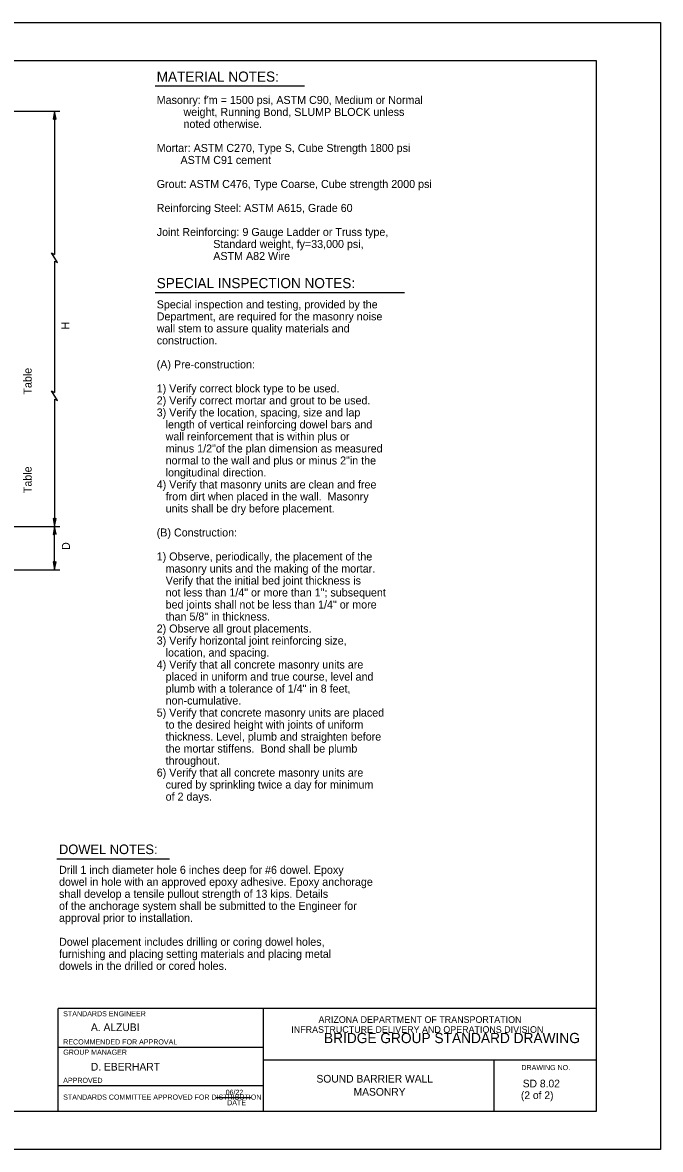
# Model space of a CAD drawing. Extents: x 0 to 2.83, y -0.03 to 1.83.
# Drawn here: x 1.796 to 2.833, y 0 to 1.833 of the extents above; entities that cross this region are included whole.
import ezdxf

# ---------------------------------------------------------------- set-up
doc = ezdxf.new("R2010")
doc.units = 0
for name, color, linetype in [('54', 7, 'Continuous'), ('55', 7, 'Continuous'), ('57', 7, 'Continuous'), ('62', 7, 'Continuous'), ('63', 7, 'Continuous')]:
    doc.layers.add(name, color=color, linetype=linetype)

msp = doc.modelspace()

# ---------------------------------------------------------------- linework, layer by layer
at = {"layer": '54'}
for points in [[(1.8485, 1.6891), (1.8461, 1.6761), (1.8485, 1.6777), (1.8509, 1.6763)], [(1.8485, 1.0136), (1.8509, 1.0266), (1.8485, 1.0251), (1.8461, 1.0264)], [(1.8485, 1.0136), (1.8461, 1.0006), (1.8485, 1.0021), (1.8509, 1.0008)], [(1.8485, 0.9429), (1.8509, 0.9559), (1.8485, 0.9544), (1.8461, 0.9558)]]:
    msp.add_lwpolyline(points, close=True, dxfattribs=at)
at = {"layer": '55'}
for p, q in [((1.5334, 1.6891), (1.8568, 1.6891)), ((1.8485, 1.6891), (1.8485, 1.4561)), ((1.8534, 1.4428), (1.8436, 1.4586)), ((1.8436, 1.4586), (1.8485, 1.4561)), ((1.8485, 1.4453), (1.8485, 1.2316)), ((1.8485, 1.4453), (1.8534, 1.4428)), ((1.8534, 1.2183), (1.8436, 1.2341)), ((1.8436, 1.2341), (1.8485, 1.2316)), ((1.8485, 1.2208), (1.8485, 1.0136)), ((1.8485, 1.2208), (1.8534, 1.2183)), ((1.6377, 1.0136), (1.8568, 1.0136)), ((1.6377, 0.9429), (1.8568, 0.9429))]:
    msp.add_line(p, q, dxfattribs=at)
at = {"layer": '57'}
for p, q in [((2.012, 1.7303), (2.2547, 1.7303)), ((2.012, 1.3944), (2.4174, 1.3944)), ((1.8485, 0.9429), (1.8485, 1.0136)), ((1.852, 0.4727), (2.0354, 0.4727))]:
    msp.add_line(p, q, dxfattribs=at)
at = {"layer": '62'}
for p, q in [((2.7292, 0.2291), (1.8542, 0.2291)), ((1.8542, 0.0624), (1.8542, 0.2291)), ((2.1875, 0.2291), (2.1875, 0.0624)), ((2.5625, 0.1458), (2.5625, 0.0624)), ((2.111, 0.0843), (2.1675, 0.0843))]:
    msp.add_line(p, q, dxfattribs=at)
at = {"layer": '63'}
for p, q in [((0, 1.8333), (2.8333, 1.8333)), ((2.8333, 1.8333), (2.8333, 0)), ((1.8542, 0.1666), (2.1875, 0.1666)), ((2.1875, 0.1458), (2.7292, 0.1458)), ((1.8542, 0.1041), (2.1875, 0.1041)), ((2.8333, 0), (0, 0))]:
    msp.add_line(p, q, dxfattribs=at)
msp.add_lwpolyline([(2.7292, 1.7708), (0.1042, 1.7708), (0.1042, 0.0624), (2.7292, 0.0624)], close=True, dxfattribs=at)

# ---------------------------------------------------------------- texts
at = {"layer": '57'}
for s, height, p in [('MATERIAL NOTES:', 0.0165, (2.0145, 1.7371)), ("Masonry: f'm = 1500 psi, ASTM C90, Medium or Normal", 0.013021, (2.0145, 1.7009)), ('         weight, Running Bond, SLUMP BLOCK unless', 0.013021, (2.0145, 1.6814)), ('         noted otherwise.', 0.013021, (2.0145, 1.6619)), ('Mortar: ASTM C270, Type S, Cube Strength 1800 psi', 0.013021, (2.0145, 1.6228)), ('        ASTM C91 cement', 0.013021, (2.0145, 1.6033)), ('Grout: ASTM C476, Type Coarse, Cube strength 2000 psi', 0.013021, (2.0145, 1.5642)), ('Reinforcing Steel: ASTM A615, Grade 60', 0.013021, (2.0145, 1.5252)), ('Joint Reinforcing: 9 Gauge Ladder or Truss type,', 0.013021, (2.0145, 1.4861)), ('                   Standard weight, fy=33,000 psi,', 0.013021, (2.0145, 1.4666)), ('                   ASTM A82 Wire', 0.013021, (2.0145, 1.447)), ('SPECIAL INSPECTION NOTES:', 0.0165, (2.0145, 1.4012)), ('Special inspection and testing, provided by the', 0.013021, (2.0145, 1.3683)), ('Department, are required for the masonry noise', 0.013021, (2.0145, 1.3488)), ('wall stem to assure quality materials and', 0.013021, (2.0145, 1.3292)), ('construction.', 0.013021, (2.0145, 1.3097)), ('(A) Pre-construction:', 0.013021, (2.0145, 1.2707)), ('1) Verify correct block type to be used.', 0.013021, (2.0145, 1.2316)), ('2) Verify correct mortar and grout to be used.', 0.013021, (2.0145, 1.2121)), ('3) Verify the location, spacing, size and lap', 0.013021, (2.0145, 1.1925)), ('   length of vertical reinforcing dowel bars and', 0.013021, (2.0145, 1.173)), ('   wall reinforcement that is within plus or', 0.013021, (2.0145, 1.1535)), ('   minus 1/2"of the plan dimension as measured', 0.013021, (2.0145, 1.1339)), ('   normal to the wall and plus or minus 2"in the', 0.013021, (2.0145, 1.1144)), ('   longitudinal direction.', 0.013021, (2.0145, 1.0949)), ('4) Verify that masonry units are clean and free', 0.013021, (2.0145, 1.0753)), ('   from dirt when placed in the wall.  Masonry', 0.013021, (2.0145, 1.0558)), ('   units shall be dry before placement.', 0.013021, (2.0145, 1.0363)), ('(B) Construction:', 0.013021, (2.0145, 0.9972)), ('1) Observe, periodically, the placement of the', 0.013021, (2.0145, 0.9582)), ('   masonry units and the making of the mortar.', 0.013021, (2.0145, 0.9386)), ('   Verify that the initial bed joint thickness is', 0.013021, (2.0145, 0.9191)), ('   not less than 1/4" or more than 1"; subsequent', 0.013021, (2.0145, 0.8996)), ('   bed joints shall not be less than 1/4" or more', 0.013021, (2.0145, 0.88)), ('   than 5/8" in thickness.', 0.013021, (2.0145, 0.8605)), ('2) Observe all grout placements.', 0.013021, (2.0145, 0.841)), ('3) Verify horizontal joint reinforcing size,', 0.013021, (2.0145, 0.8214)), ('   location, and spacing.', 0.013021, (2.0145, 0.8019)), ('4) Verify that all concrete masonry units are', 0.013021, (2.0145, 0.7824)), ('   placed in uniform and true course, level and', 0.013021, (2.0145, 0.7628)), ('   plumb with a tolerance of 1/4" in 8 feet,', 0.013021, (2.0145, 0.7433)), ('   non-cumulative.', 0.013021, (2.0145, 0.7238)), ('5) Verify that concrete masonry units are placed', 0.013021, (2.0145, 0.7042)), ('   to the desired height with joints of uniform', 0.013021, (2.0145, 0.6847)), ('   thickness. Level, plumb and straighten before', 0.013021, (2.0145, 0.6652)), ('   the mortar stiffens.  Bond shall be plumb', 0.013021, (2.0145, 0.6457)), ('   throughout.', 0.013021, (2.0145, 0.6261)), ('6) Verify that all concrete masonry units are', 0.013021, (2.0145, 0.6066)), ('   cured by sprinkling twice a day for minimum', 0.013021, (2.0145, 0.5871)), ('   of 2 days.', 0.013021, (2.0145, 0.5675)), ('DOWEL NOTES:', 0.015625, (1.8557, 0.4805)), ('Drill 1 inch diameter hole 6 inches deep for #6 dowel. Epoxy ', 0.013021, (1.8557, 0.4484)), ('dowel in hole with an approved epoxy adhesive. Epoxy anchorage ', 0.013021, (1.8557, 0.4289)), ('shall develop a tensile pullout strength of 13 kips. Details ', 0.013021, (1.8557, 0.4094)), ('of the anchorage system shall be submitted to the Engineer for ', 0.013021, (1.8557, 0.3898)), ('approval prior to installation.', 0.013021, (1.8557, 0.3703)), ('Dowel placement includes drilling or coring dowel holes, ', 0.013021, (1.8557, 0.3313)), ('furnishing and placing setting materials and placing metal ', 0.013021, (1.8557, 0.3117)), ('dowels in the drilled or cored holes. ', 0.013021, (1.8557, 0.2922))]:
    msp.add_text(s, height=height, dxfattribs=at).set_placement(p)
for s, height, p in [('H', 0.013, (1.8726, 1.3338)), ('Table', 0.01302, (1.8111, 1.2281)), ('Table', 0.01302, (1.8111, 1.0677)), ('D', 0.013, (1.8734, 0.9753))]:
    msp.add_text(s, height=height, rotation=90, dxfattribs=at).set_placement(p)
at = {"layer": '62'}
for s, height, p in [('STANDARDS ENGINEER', 0.008333, (1.8625, 0.2166)), ('     A. ALZUBI     ', 0.0125, (1.8844, 0.1926)), ('ARIZONA DEPARTMENT OF TRANSPORTATION', 0.010833, (2.2775, 0.2059)), ('INFRASTRUCTURE DELIVERY AND OPERATIONS DIVISION', 0.010833, (2.2333, 0.1897)), ('BRIDGE GROUP STANDARD DRAWING', 0.016667, (2.2864, 0.173)), ('RECOMMENDED FOR APPROVAL', 0.008333, (1.8625, 0.1708)), ('GROUP MANAGER', 0.008333, (1.8625, 0.1541)), ('     D. EBERHART      ', 0.0125, (1.8842, 0.1283)), ('DRAWING NO.', 0.008333, (2.6073, 0.1291)), ('APPROVED', 0.00833, (1.8625, 0.1083)), ('SOUND BARRIER WALL', 0.0125, (2.2742, 0.1088)), ('SD 8.02  ', 0.0125, (2.6095, 0.101)), ('06/22', 0.00833, (2.1265, 0.0888)), ('MASONRY', 0.0125, (2.3345, 0.0875)), ('(2 of 2)  ', 0.0125, (2.6065, 0.082)), ('STANDARDS COMMITTEE APPROVED FOR DISTRIBUTION', 0.008333, (1.8625, 0.081)), ('DATE', 0.00833, (2.129, 0.0718))]:
    msp.add_text(s, height=height, dxfattribs=at).set_placement(p)

doc.saveas('drawing.dxf')
